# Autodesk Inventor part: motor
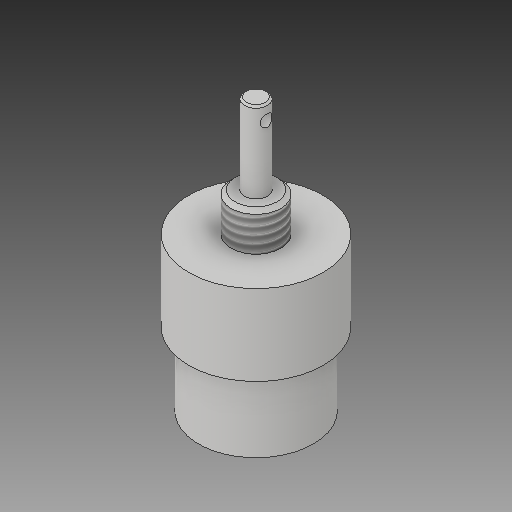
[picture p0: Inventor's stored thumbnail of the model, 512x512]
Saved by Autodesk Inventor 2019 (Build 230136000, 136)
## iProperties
Created: 2019-10
Part Number: motor
Material: Generic
Document SubType Name: Modeling
Designer: Asus
Density: 1 g/cm^3
Appearance: Default
Author: Asus
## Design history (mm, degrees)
sketch "Sketch1"
  geometry: C1 r 6.5 at (0, 0); 1 further point
  constraints: 1 centre point, 1 coincident
  dimensions: "d0" = 13 diameter of C1
extrude "Extrusion1" new body sketch "Sketch1" distance "d1" = 10; taper "d2" = 0 deg
sketch "Sketch2"
  geometry: 1 further point
sketch "Sketch3"
  geometry: C1 r 17.5 at (0, 0); 1 further point
  constraints: 1 centre point, 1 coincident
  dimensions: "d3" = 35 diameter of C1
extrude "Extrusion2" join sketch "Sketch3" distance "d4" = 21; taper "d5" = 0 deg
sketch "Sketch4"
  geometry: C1 r 15 at (0, 0); 1 further point
  constraints: 1 centre point, 1 coincident
  dimensions: "d6" = 30 diameter of C1
extrude "Extrusion3" join sketch "Sketch4" distance "d7" = 19; taper "d8" = 0 deg
sketch "Sketch5"
  geometry: C1 r 3 at (0, 0); 1 further point
  constraints: 1 centre point, 1 coincident
  dimensions: "d9" = 6 diameter of C1
extrude "Extrusion4" join sketch "Sketch5" distance "d10" = 21; taper "d11" = 0 deg
chamfer "Chamfer1" distance "d12" = 1; stored, may be unused: second distance "d13" = 2, angle "d14" = 45 deg
chamfer "Chamfer2" distance "d15" = 0.5; stored, may be unused: second distance "d16" = 2, angle "d17" = 45 deg
thread "Thread1" dims "d18" = 10, "d19" = 0
sketch "Sketch6"
  geometry: C1 r 1.55 at (27.143, 0); 1 further point
  constraints: 1 centre point
  dimensions: "d20" = 3.1 diameter of C1
extrude "Extrusion5" cut sketch "Sketch6" stored distance "d21" = 6; taper "d22" = 0 deg
sketch "Sketch7"
  geometry: L1 (12.192, 2.12)-(11.485, 2.12); L2 (11.485, 2.12)-(11.485, -2.356); L3 (11.485, -2.356)-(12.192, -2.356); L4 (12.192, -2.356)-(12.192, 2.12); L5 (-11.603, 2.12)-(-12.546, 2.12); L6 (-12.546, 2.12)-(-12.546, -2.356); L7 (-12.546, -2.356)-(-11.603, -2.356); L8 (-11.603, -2.356)-(-11.603, 2.12); 1 further point
  constraints: 16 end point, 4 parallel, 2 horizontal, 2 perpendicular, 2 point on line
extrude "Extrusion6" join sketch "Sketch7" distance "d23" = 1; taper "d24" = 0 deg
body "Solid1"
